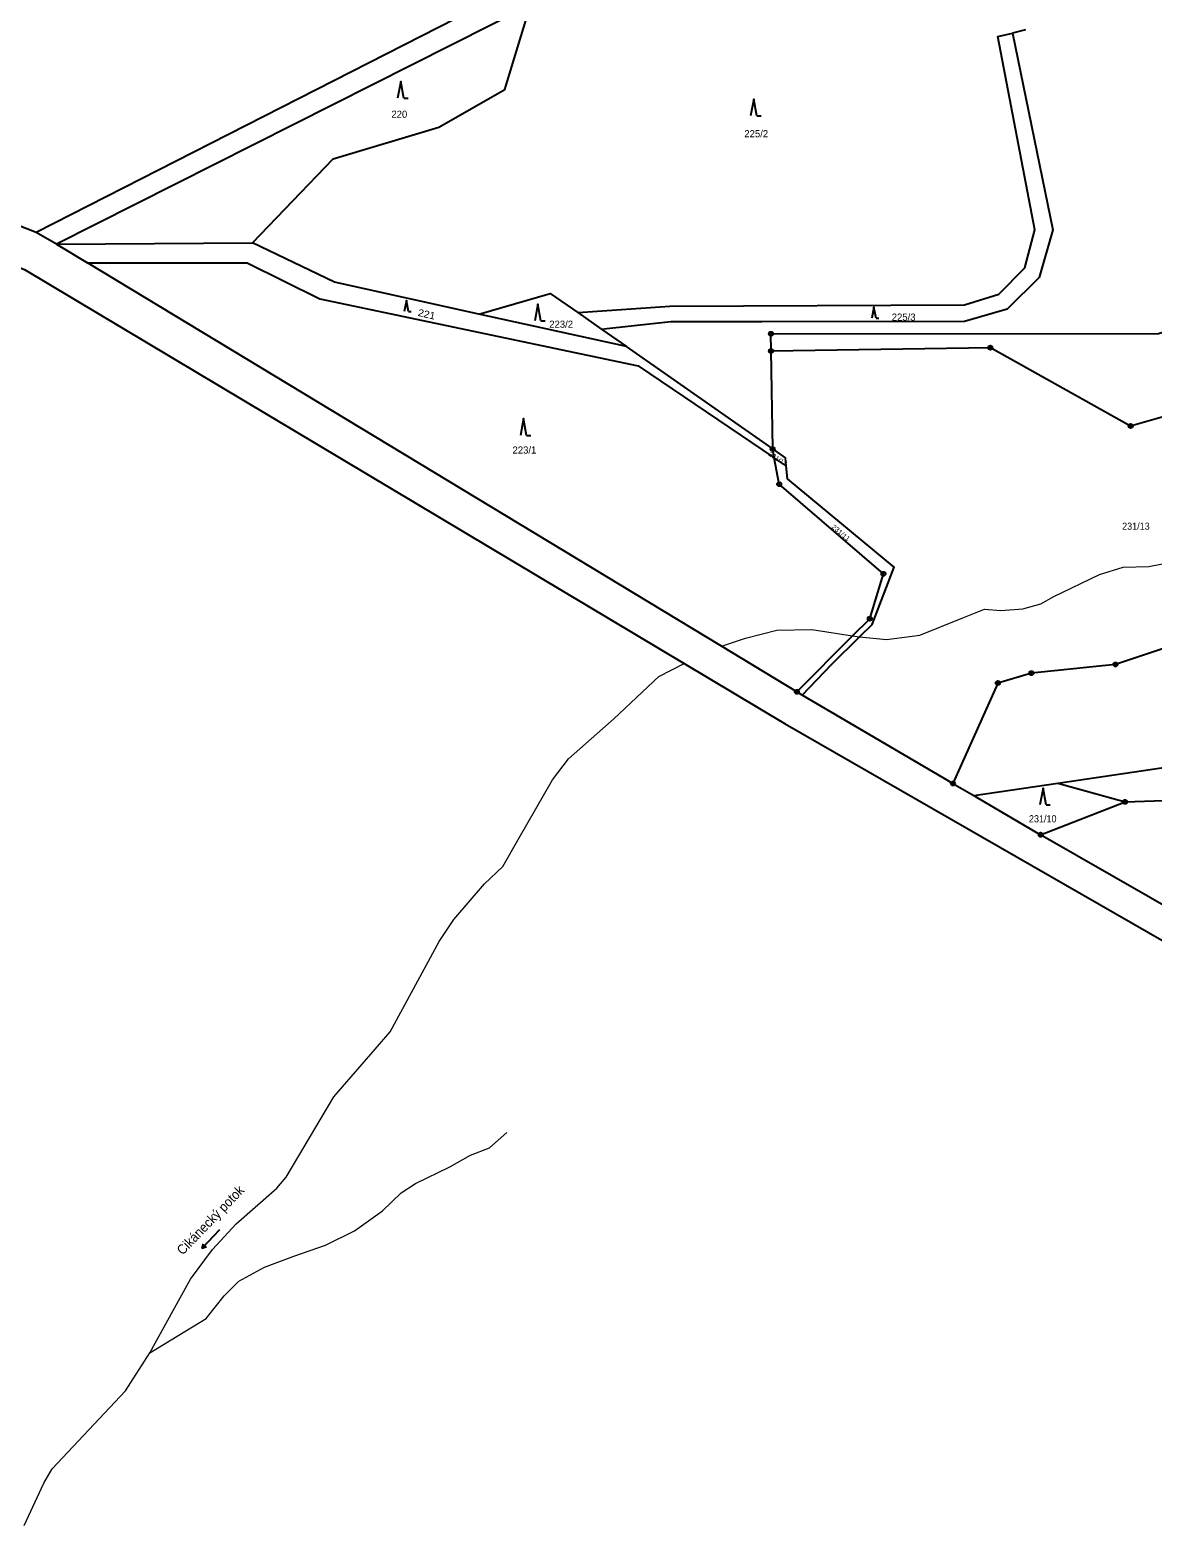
# Model space of a CAD drawing. Extents: x -632162 to -629607, y -1101195 to -1098670.
# Drawn here: x -631261.3 to -630992.8, y -1100113.2 to -1099752.9 of the extents above; entities that cross this region are included whole.
import ezdxf
from ezdxf.enums import TextEntityAlignment as Align

# ---------------------------------------------------------------- set-up
doc = ezdxf.new("R2010")
doc.units = 0
doc.header["$LTSCALE"] = 0.68
for name, color, linetype, lineweight in [('1', 7, 'Continuous', 25), ('3', 7, 'Continuous', 25), ('4', 7, 'Continuous', 13), ('7', 7, 'Continuous', 13), ('8', 7, 'Continuous', 25)]:
    doc.layers.add(name, color=color, linetype=linetype, lineweight=lineweight)
doc.layers.add('2', color=7, linetype='Continuous')

msp = doc.modelspace()

# ---------------------------------------------------------------- linework, layer by layer
at = {"layer": '1'}
for p, q in [((-631023.23, -1099752.8), (-631026.33, -1099753.56)), ((-631254.98, -1099804.01), (-631259.83, -1099801.22)), ((-631254.98, -1099804.01), (-631247.53, -1099808.49)), ((-631084.09, -1099829.53), (-631031.66, -1099828.74)), ((-631083.7, -1099852.95), (-631084.09, -1099829.53)), ((-631080.46, -1099856.97), (-631083.32, -1099855.03)), ((-631029.86, -1099908.89), (-631040.6, -1099932.89)), ((-630220.5, -1100403.45), (-631019.63, -1099945.14))]:
    msp.add_line(p, q, dxfattribs=at)
for points in [[(-631573.73, -1099649.04), (-631561.78, -1099657.37), (-631473.19, -1099721.18), (-631427.36, -1099745.46), (-631262.62, -1099810.08), (-631104.85, -1099904.21), (-631080.72, -1099918.6), (-630227.98, -1100408.08)], [(-631001.85, -1099672.16), (-631021.44, -1099685.96), (-631093.61, -1099716.5), (-631142.66, -1099741.51), (-631259.83, -1099801.22)], [(-631259.83, -1099801.22), (-631423.81, -1099736.81), (-631440.94, -1099728.4)], [(-631141.59, -1099746.86), (-631254.98, -1099804.01), (-631208.09, -1099803.66)], [(-631208.09, -1099803.66), (-631188.84, -1099783.64), (-631163.54, -1099776.07), (-631147.77, -1099767.07), (-631141.59, -1099746.86)], [(-631108.32, -1099818.86), (-631037.81, -1099818.54), (-631029.64, -1099815.93), (-631023.42, -1099809.65), (-631021.02, -1099800.58), (-631029.9, -1099754.35), (-631026.33, -1099753.56)], [(-631026.33, -1099753.56), (-631016.74, -1099800.62), (-631019.96, -1099811.98), (-631027.63, -1099819.53), (-631037.86, -1099822.47)], [(-631154, -1099820.72), (-631188.5, -1099813.11), (-631208.09, -1099803.66)], [(-631247.53, -1099808.49), (-631209.37, -1099808.47), (-631192.02, -1099817.05), (-631115.87, -1099833.07), (-631083.32, -1099855.03)], [(-631077.92, -1099910.99), (-631095.94, -1099900.1), (-631247.53, -1099808.49)], [(-631084.09, -1099829.53), (-631084.12, -1099825.43), (-630991.45, -1099825.32), (-630936.33, -1099808.78), (-630930.38, -1099826.1)], [(-631154, -1099820.72), (-631136.9, -1099815.77), (-631130.32, -1099820.37), (-631124.54, -1099824.41)], [(-631083.32, -1099855.03), (-631083.7, -1099852.95), (-631118.68, -1099828.5), (-631154, -1099820.72)], [(-631130.32, -1099820.37), (-631129.08, -1099820.28), (-631108.32, -1099818.86)], [(-631037.86, -1099822.47), (-631086.33, -1099822.54), (-631108.06, -1099822.57), (-631123.34, -1099824.28), (-631124.54, -1099824.41), (-631118.68, -1099828.5)], [(-631031.66, -1099828.74), (-630998.12, -1099847.45), (-630981.93, -1099842.81), (-630957.14, -1099839.65), (-630947.77, -1099831.91), (-630934.02, -1099827.32)], [(-631080.46, -1099856.97), (-631080.66, -1099855.08), (-631083.7, -1099852.95)], [(-631077.92, -1099910.99), (-631064.59, -1099897.62), (-631060.49, -1099893.51), (-631057.22, -1099882.78), (-631082.14, -1099861.36), (-631083.32, -1099855.03)], [(-631076.62, -1099911.75), (-631069.6, -1099904.4), (-631062.92, -1099897.82), (-631059.93, -1099894.88), (-631054.67, -1099881.16), (-631080.18, -1099860.09), (-631080.46, -1099856.97)], [(-631040.6, -1099932.89), (-631035.61, -1099935.8), (-631015.53, -1099932.83), (-630955.16, -1099923.88), (-630943.43, -1099881.3), (-630964.68, -1099888.97)], [(-630964.68, -1099888.97), (-630969.01, -1099891.48), (-630979.34, -1099896.94), (-631001.73, -1099904.44), (-631021.83, -1099906.52), (-631029.86, -1099908.89)], [(-631040.6, -1099932.89), (-631076.62, -1099911.75), (-631077.92, -1099910.99)], [(-631015.53, -1099932.83), (-630999.45, -1099937.29), (-630990.18, -1099936.98)], [(-631035.61, -1099935.8), (-631034.55, -1099936.42), (-631019.63, -1099945.14), (-630999.45, -1099937.29)]]:
    msp.add_lwpolyline(points, dxfattribs=at)
at = {"layer": '3'}
for p, q in [((-631171.89, -1099769.1), (-631170.894, -1099769.1)), ((-631087.49, -1099773.36), (-631086.494, -1099773.36)), ((-631170.808, -1099820.12), (-631170.14, -1099820.12)), ((-631058.998, -1099821.72), (-631058.33, -1099821.72)), ((-631139.11, -1099822.33), (-631138.114, -1099822.33)), ((-631142.54, -1099849.7), (-631141.544, -1099849.7)), ((-631018.31, -1099938.01), (-631017.314, -1099938.01)), ((-631220.114, -1100043.931), (-631219.814, -1100042.874))]:
    msp.add_line(p, q, dxfattribs=at)
for points in [[(-631171.89, -1099769.1), (-631172.64, -1099765.1), (-631173.39, -1099769.1)], [(-631087.49, -1099773.36), (-631088.24, -1099769.36), (-631088.99, -1099773.36)], [(-631170.808, -1099820.12), (-631171.31, -1099817.44), (-631171.812, -1099820.12)], [(-631139.11, -1099822.33), (-631139.86, -1099818.33), (-631140.61, -1099822.33)], [(-631058.998, -1099821.72), (-631059.5, -1099819.04), (-631060.002, -1099821.72)], [(-631142.54, -1099849.7), (-631143.29, -1099845.7), (-631144.04, -1099849.7)], [(-631018.31, -1099938.01), (-631019.06, -1099934.01), (-631019.81, -1099938.01)], [(-631216.022, -1100039.543), (-631220.114, -1100043.931), (-631219.081, -1100043.558)]]:
    msp.add_lwpolyline(points, dxfattribs=at)
at = {"layer": '4'}
for p, q in [((-631016.46, -1099888.21), (-631005.57, -1099882.98)), ((-631005.57, -1099882.98), (-630999.86, -1099881.23)), ((-630999.86, -1099881.23), (-630993.79, -1099881.05)), ((-630993.79, -1099881.05), (-630990.11, -1099880.31)), ((-631023.91, -1099891.16), (-631019.59, -1099889.96)), ((-631019.59, -1099889.96), (-631016.46, -1099888.21)), ((-631048.49, -1099897.42), (-631038.27, -1099893.28)), ((-631038.27, -1099893.28), (-631033.02, -1099891.25)), ((-631033.02, -1099891.25), (-631029.16, -1099891.53)), ((-631029.16, -1099891.53), (-631023.91, -1099891.16)), ((-631090.18, -1099898.16), (-631082.72, -1099896.22)), ((-631082.72, -1099896.22), (-631074.35, -1099896.13)), ((-631074.35, -1099896.13), (-631064.59, -1099897.62)), ((-631095.94, -1099900.1), (-631090.18, -1099898.16)), ((-631064.59, -1099897.62), (-631062.92, -1099897.82)), ((-631062.92, -1099897.82), (-631056.49, -1099898.52)), ((-631056.49, -1099898.52), (-631048.49, -1099897.42)), ((-631110.91, -1099907.29), (-631104.85, -1099904.21)), ((-631121.7, -1099917.43), (-631110.91, -1099907.29)), ((-631132.5, -1099927.02), (-631121.7, -1099917.43)), ((-631136.34, -1099932.02), (-631132.5, -1099927.02)), ((-631144.29, -1099945.9), (-631136.34, -1099932.02)), ((-631148.23, -1099952.71), (-631144.29, -1099945.9)), ((-631152.65, -1099956.9), (-631148.23, -1099952.71)), ((-631159.95, -1099965.37), (-631152.65, -1099956.9)), ((-631163.44, -1099970.66), (-631159.95, -1099965.37)), ((-631175.2, -1099992.23), (-631163.44, -1099970.66)), ((-631178.74, -1099996.41), (-631175.2, -1099992.23)), ((-631188.62, -1100007.74), (-631178.74, -1099996.41)), ((-631200.06, -1100026.97), (-631188.62, -1100007.74)), ((-631151.46, -1100019.98), (-631147.28, -1100016.26)), ((-631160.87, -1100024.51), (-631155.99, -1100021.72)), ((-631155.99, -1100021.72), (-631151.46, -1100019.98)), ((-631202.31, -1100029.62), (-631200.06, -1100026.97)), ((-631169.12, -1100028.52), (-631160.87, -1100024.51)), ((-631212.01, -1100038.16), (-631202.31, -1100029.62)), ((-631172.55, -1100030.73), (-631169.12, -1100028.52)), ((-631177.02, -1100035.03), (-631172.55, -1100030.73)), ((-631183.67, -1100039.77), (-631177.02, -1100035.03)), ((-631217.68, -1100044.23), (-631212.01, -1100038.16)), ((-631190.64, -1100043.19), (-631183.67, -1100039.77)), ((-631222.96, -1100051.37), (-631217.68, -1100044.23)), ((-631198.19, -1100045.87), (-631190.64, -1100043.19)), ((-631211.37, -1100051.79), (-631205.22, -1100048.48)), ((-631205.22, -1100048.48), (-631198.19, -1100045.87)), ((-631227.03, -1100058.81), (-631222.96, -1100051.37)), ((-631214.86, -1100055.34), (-631211.37, -1100051.79)), ((-631219.19, -1100060.76), (-631214.86, -1100055.34)), ((-631232.67, -1100068.95), (-631227.03, -1100058.81)), ((-631232.67, -1100068.95), (-631219.19, -1100060.76)), ((-631238.44, -1100078.06), (-631232.67, -1100068.95)), ((-631255.97, -1100096.69), (-631238.44, -1100078.06)), ((-631258, -1100100.11), (-631255.97, -1100096.69)), ((-631262.71, -1100110.22), (-631258, -1100100.11))]:
    msp.add_line(p, q, dxfattribs=at)
at = {"layer": '8'}
for centre, radius in [((-631084.12, -1099825.4299), 0.5), ((-631084.12, -1099825.4299), 0.0303), ((-631031.66, -1099828.7399), 0.5), ((-631031.66, -1099828.7399), 0.0303), ((-631084.09, -1099829.5299), 0.5), ((-631084.09, -1099829.5299), 0.0303), ((-630998.12, -1099847.4499), 0.5), ((-630998.12, -1099847.4499), 0.0303), ((-631083.7, -1099852.9499), 0.5), ((-631083.7, -1099852.9499), 0.0303), ((-631082.14, -1099861.3599), 0.5), ((-631082.14, -1099861.3599), 0.0303), ((-631057.22, -1099882.7799), 0.5), ((-631057.22, -1099882.7799), 0.0303), ((-631060.49, -1099893.5099), 0.5), ((-631060.49, -1099893.5099), 0.0303), ((-631001.73, -1099904.4399), 0.5), ((-631001.73, -1099904.4399), 0.0303), ((-631021.83, -1099906.5199), 0.5), ((-631021.83, -1099906.5199), 0.0303), ((-631077.92, -1099910.9899), 0.5), ((-631077.92, -1099910.9899), 0.0303), ((-631029.86, -1099908.8899), 0.5), ((-631029.86, -1099908.8899), 0.0303), ((-631040.6, -1099932.8899), 0.5), ((-631040.6, -1099932.8899), 0.0303), ((-630999.45, -1099937.2899), 0.5), ((-630999.45, -1099937.2899), 0.0303), ((-631019.63, -1099945.1399), 0.5), ((-631019.63, -1099945.1399), 0.0303)]:
    msp.add_circle(centre, radius, dxfattribs=at)

# ---------------------------------------------------------------- texts
at = {"layer": '2'}
for s, p in [('220', (-631172.989, -1099773.8)), ('225/2', (-631087.64, -1099778.46)), ('225/3', (-631052.39, -1099822.29)), ('223/2', (-631134.29, -1099823.98)), ('223/1', (-631143.07, -1099854.05))]:
    msp.add_text(s, height=1.7, dxfattribs=at).set_placement(p, align=Align.CENTER)
for s, height, rotation, width, p in [('221', 1.7, 347, 1.1, (-631166.6337, -1099821.5866)), ('231/12', 1.14, 327, 1.05, (-631082.7624, -1099855.782)), ('231/11', 1.14, 320, 1.1, (-631067.7514, -1099873.411))]:
    msp.add_text(s, height=height, rotation=rotation, dxfattribs=dict(at, width=width)).set_placement(p, align=Align.CENTER)
at = {"layer": '2', "width": 0.95}
for s, p in [('231/13', (-630996.849, -1099872.25)), ('231/10', (-631019.129, -1099942.17))]:
    msp.add_text(s, height=1.7, dxfattribs=at).set_placement(p, align=Align.CENTER)
at = {"layer": '7', "width": 0.95}
msp.add_text('Cikánecký potok', height=2.3, rotation=46, dxfattribs=at).set_placement((-631217.3463, -1100038.0189), align=Align.CENTER)

doc.saveas('drawing.dxf')
